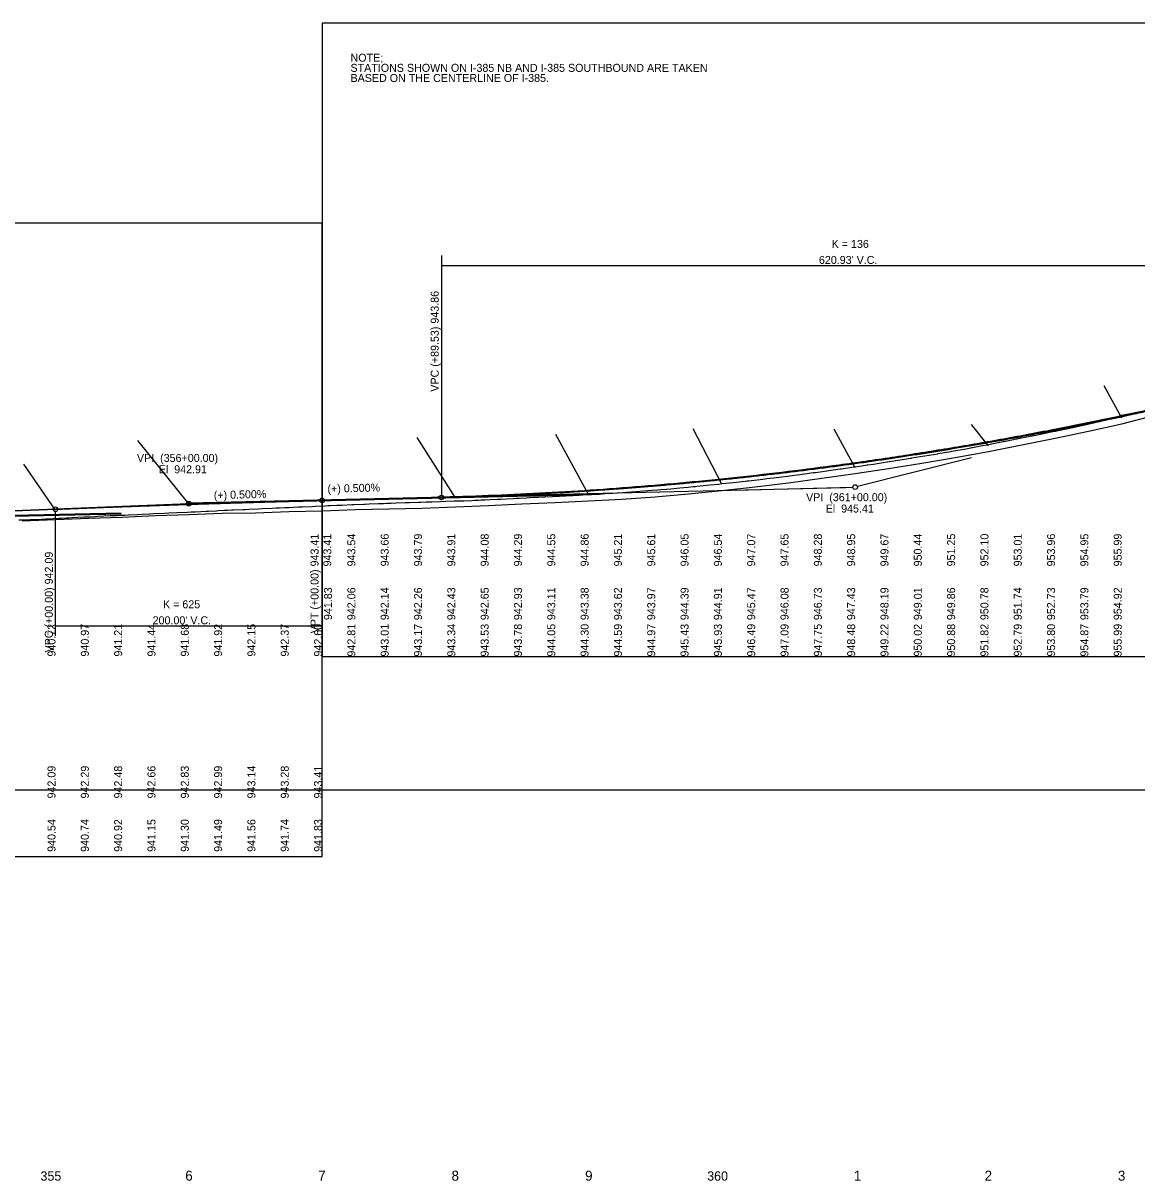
# Model space of a CAD drawing. Extents: x 120 to 1628239, y 505 to 1092823.
# Drawn here: x 1616014 to 1616850, y 1076164 to 1077032 of the extents above; entities that cross this region are included whole.
import ezdxf

# ---------------------------------------------------------------- set-up
doc = ezdxf.new("R2010")
doc.units = 0
for name, color, linetype in [('Default', 7, 'Continuous'), ('RD_DDB_GradeTX', 7, 'Continuous'), ('RD_DDB_PI', 7, 'Continuous'), ('RD_DDB_PR_Tx', 7, 'Continuous'), ('RD_DDB_Profile_EX', 7, 'Continuous'), ('RD_DDB_Profile_PR', 7, 'Continuous'), ('RD_DDB_StaTX', 7, 'Continuous'), ('RD_DDB_StripGrade', 7, 'Continuous'), ('RD_DDB_StripGrade_PR', 7, 'Continuous'), ('RD_DDB_VCLbl', 7, 'Continuous'), ('RD_GPK_Profile_Cell', 7, 'Continuous'), ('RD_PD_Final_TrvlWay', 7, 'Continuous'), ('RD_Sketch10', 7, 'Continuous')]:
    doc.layers.add(name, color=color, linetype=linetype)

msp = doc.modelspace()

# ---------------------------------------------------------------- linework, layer by layer
at = {"layer": 'Default'}
for p, q in [((1616138.64, 1076672.71), (1616631.44, 1076684.04)), ((1615838.64, 1076659.56), (1616138.64, 1076671.86)), ((1616238.64, 1076674.36), (1616318.64, 1076676.36)), ((1615938.64, 1076663.66), (1616038.64, 1076667.76))]:
    msp.add_line(p, q, dxfattribs=at)
for points in [[(1616238.64, 1076557.31), (1617738.64, 1076557.31), (1617738.64, 1077032.31), (1616238.64, 1077032.31)], [(1614738.64, 1076407.31), (1616238.64, 1076407.31), (1616238.64, 1076882.31), (1614738.64, 1076882.31)]]:
    msp.add_lwpolyline(points, close=True, dxfattribs=at)
for points in [[(1616318.64, 1076676.36), (1616638.64, 1076684.36), (1616958.64, 1076765.41)], [(1616320.44, 1076676.89), (1616631.44, 1076684.04), (1616942.44, 1076762.31)], [(1616038.64, 1076667.76), (1616138.64, 1076671.86), (1616238.64, 1076674.36)]]:
    msp.add_open_spline(points, degree=2, dxfattribs=at)
at = {"layer": 'RD_DDB_PI'}
for p, q in [((1616725.89, 1076706.46), (1616640.34, 1076684.79)), ((1616548.67, 1076682.11), (1616636.89, 1076684.31)), ((1616048.72, 1076668.17), (1616136.89, 1076671.79)), ((1616228.61, 1076674.11), (1616140.39, 1076671.9))]:
    msp.add_line(p, q, dxfattribs=at)
for centre in [(1616638.64, 1076684.36), (1616138.64, 1076671.86)]:
    msp.add_circle(centre, 1.75, dxfattribs=at)
at = {"layer": 'RD_DDB_Profile_EX'}
msp.add_lwpolyline([(1616013.64, 1076659.1), (1616038.64, 1076659.99), (1616063.64, 1076661.01), (1616088.64, 1076661.91), (1616113.64, 1076663.05), (1616138.64, 1076663.79), (1616163.64, 1076664.74), (1616188.64, 1076665.11), (1616213.64, 1076665.99), (1616238.64, 1076666.47), (1616263.64, 1076667.63), (1616288.64, 1076668.02), (1616313.64, 1076668.59), (1616338.64, 1076669.48), (1616363.64, 1076670.56), (1616388.64, 1076671.94), (1616413.64, 1076672.84), (1616438.64, 1076674.2), (1616463.64, 1076675.43), (1616488.64, 1076677.14), (1616513.64, 1076679.25), (1616538.64, 1076681.86), (1616563.64, 1076684.65), (1616588.64, 1076687.7), (1616613.64, 1076690.97), (1616638.64, 1076694.47), (1616663.64, 1076698.28), (1616688.64, 1076702.34), (1616713.64, 1076706.62), (1616738.64, 1076711.21), (1616763.64, 1076715.99), (1616788.64, 1076720.97), (1616813.64, 1076726.27), (1616838.64, 1076731.9), (1616863.64, 1076738.25)], dxfattribs=at)
at = {"layer": 'RD_DDB_Profile_PR'}
for p, q in [((1616238.64, 1076674.36), (1616328.18, 1076676.6)), ((1615938.64, 1076663.66), (1616038.64, 1076667.76))]:
    msp.add_line(p, q, dxfattribs=at)
for points in [[(1616328.18, 1076676.6), (1616340.59, 1076676.94), (1616353.01, 1076677.33), (1616365.43, 1076677.78), (1616377.85, 1076678.29), (1616390.27, 1076678.86), (1616402.69, 1076679.48), (1616415.11, 1076680.16), (1616427.52, 1076680.9), (1616439.94, 1076681.69), (1616452.36, 1076682.54), (1616464.78, 1076683.44), (1616477.2, 1076684.4), (1616489.62, 1076685.42), (1616502.04, 1076686.5), (1616514.46, 1076687.63), (1616526.87, 1076688.82), (1616539.29, 1076690.07), (1616551.71, 1076691.37), (1616564.13, 1076692.73), (1616576.55, 1076694.15), (1616588.97, 1076695.62), (1616601.39, 1076697.15), (1616613.8, 1076698.73), (1616626.22, 1076700.38), (1616638.64, 1076702.08), (1616651.06, 1076703.83), (1616663.48, 1076705.65), (1616675.9, 1076707.52), (1616688.32, 1076709.44), (1616700.73, 1076711.43), (1616713.15, 1076713.47), (1616725.57, 1076715.56), (1616737.99, 1076717.72), (1616750.41, 1076719.93), (1616762.83, 1076722.19), (1616775.25, 1076724.51), (1616787.67, 1076726.89), (1616800.08, 1076729.33), (1616812.5, 1076731.83), (1616824.92, 1076734.38), (1616837.34, 1076736.98), (1616849.76, 1076739.65), (1616862.18, 1076742.37), (1616874.6, 1076745.14), (1616887.01, 1076747.98), (1616899.43, 1076750.87), (1616911.85, 1076753.81), (1616924.27, 1076756.82), (1616936.69, 1076759.88), (1616949.11, 1076762.99)], [(1616038.64, 1076667.76), (1616042.64, 1076667.92), (1616046.64, 1076668.08), (1616050.64, 1076668.24), (1616054.64, 1076668.4), (1616058.64, 1076668.56), (1616062.64, 1076668.72), (1616066.64, 1076668.88), (1616070.64, 1076669.03), (1616074.64, 1076669.18), (1616078.64, 1076669.33), (1616082.64, 1076669.49), (1616086.64, 1076669.63), (1616090.64, 1076669.78), (1616094.64, 1076669.93), (1616098.64, 1076670.07), (1616102.64, 1076670.22), (1616106.64, 1076670.36), (1616110.64, 1076670.5), (1616114.64, 1076670.64), (1616118.64, 1076670.78), (1616122.64, 1076670.92), (1616126.64, 1076671.06), (1616130.64, 1076671.19), (1616134.64, 1076671.33), (1616138.64, 1076671.46), (1616142.64, 1076671.59), (1616146.64, 1076671.72), (1616150.64, 1076671.85), (1616154.64, 1076671.98), (1616158.64, 1076672.1), (1616162.64, 1076672.23), (1616166.64, 1076672.35), (1616170.64, 1076672.47), (1616174.64, 1076672.59), (1616178.64, 1076672.71), (1616182.64, 1076672.83), (1616186.64, 1076672.95), (1616190.64, 1076673.07), (1616194.64, 1076673.18), (1616198.64, 1076673.29), (1616202.64, 1076673.41), (1616206.64, 1076673.52), (1616210.64, 1076673.63), (1616214.64, 1076673.74), (1616218.64, 1076673.84), (1616222.64, 1076673.95), (1616226.64, 1076674.05), (1616230.64, 1076674.16), (1616234.64, 1076674.26), (1616238.64, 1076674.36)]]:
    msp.add_spline(points, degree=3, dxfattribs=at)
at = {"layer": 'RD_DDB_VCLbl'}
for p, q in [((1616328.18, 1076857.99), (1616328.18, 1076678.35)), ((1616328.18, 1076850.49), (1616949.11, 1076850.49)), ((1616238.64, 1076572.76), (1616238.64, 1076672.61)), ((1616038.64, 1076572.76), (1616038.64, 1076666.01)), ((1616038.64, 1076580.26), (1616238.64, 1076580.26))]:
    msp.add_line(p, q, dxfattribs=at)
for centre in [(1616328.18, 1076676.6), (1616038.64, 1076667.76), (1616238.64, 1076674.36)]:
    msp.add_circle(centre, 1.75, dxfattribs=at)
at = {"layer": 'RD_GPK_Profile_Cell'}
msp.add_line((1609538.64, 1076457.31), (1626874.64, 1076457.31), dxfattribs=at)
at = {"layer": 'RD_PD_Final_TrvlWay'}
for p, q in [((1616838.64, 1076736.06), (1616825.41, 1076760.22)), ((1616738.64, 1076715.46), (1616725.99, 1076731.3)), ((1616338.64, 1076676.36), (1616309.94, 1076721.59)), ((1616438.64, 1076678.76), (1616414.12, 1076723.93)), ((1616538.64, 1076686.51), (1616516.98, 1076728.03)), ((1616638.64, 1076698.86), (1616622.91, 1076727.8)), ((1616138.64, 1076671.86), (1616100.42, 1076719.25)), ((1616038.64, 1076667.06), (1616014.98, 1076701.68)), ((1616138.64, 1076672.71), (1616438.64, 1076679.61)), ((1616138.64, 1076671.86), (1616438.64, 1076678.76)), ((1616138.64, 1076671.86), (1615838.64, 1076659.56)), ((1614737.59, 1076634.58), (1616087.83, 1076665.19)), ((1614737.59, 1076633.73), (1616087.83, 1076664.34))]:
    msp.add_line(p, q, dxfattribs=at)
at = {"layer": 'RD_Sketch10'}
for points in [[(1616652.36, 1076701.71), (1616662.5, 1076703.26), (1616662.8, 1076703.3), (1616670.76, 1076704.55), (1616670.87, 1076704.57), (1616680.28, 1076706.12), (1616680.83, 1076706.21), (1616680.84, 1076706.22), (1616690.7, 1076707.76), (1616690.89, 1076707.79), (1616697.35, 1076708.88), (1616700.56, 1076709.44), (1616701.03, 1076709.52), (1616710.55, 1076711.15), (1616711.16, 1076711.27), (1616720.46, 1076712.9), (1616720.81, 1076712.96), (1616726.25, 1076714.03), (1616726.75, 1076714.12), (1616730.37, 1076714.77), (1616731.35, 1076714.97), (1616740.3, 1076716.71), (1616741, 1076716.83), (1616749.8, 1076718.59), (1616750.23, 1076718.67), (1616751.43, 1076718.91), (1616759.69, 1076720.46), (1616760.17, 1076720.56), (1616760.99, 1076720.72), (1616770.05, 1076722.55), (1616771.61, 1076722.87), (1616779.94, 1076724.49), (1616780.97, 1076724.71), (1616788.14, 1076726.23), (1616788.97, 1076726.4), (1616790.99, 1076726.79), (1616799.73, 1076728.63), (1616800.41, 1076728.78), (1616802.01, 1076729.1), (1616809.63, 1076730.71), (1616812.13, 1076731.3), (1616819.53, 1076733), (1616822.08, 1076733.6), (1616829.23, 1076735.23), (1616831.66, 1076735.71), (1616833.85, 1076736.16), (1616840.52, 1076737.69), (1616842.46, 1076738.17)], [(1616249.67, 1076670.73), (1616250.95, 1076670.79), (1616253.79, 1076670.94), (1616260.95, 1076671.25), (1616262.76, 1076671.35), (1616269.88, 1076671.59), (1616270.95, 1076671.65), (1616273.89, 1076671.78), (1616280.94, 1076672.1), (1616284.74, 1076672.19), (1616287.19, 1076672.31), (1616290.38, 1076672.46), (1616294.13, 1076672.58), (1616301.12, 1076672.82), (1616304.14, 1076672.91), (1616311.11, 1076673.07), (1616312.77, 1076673.13), (1616316.75, 1076673.27), (1616318.37, 1076673.32), (1616321.11, 1076673.36), (1616327.58, 1076673.55), (1616331.56, 1076673.72), (1616337.83, 1076673.99), (1616341.09, 1076674.06), (1616344.94, 1076674.19), (1616351.09, 1076674.46), (1616352.96, 1076674.55), (1616355.91, 1076674.66), (1616358.06, 1076674.75), (1616361.08, 1076674.86), (1616364.51, 1076675.01), (1616370.39, 1076675.29), (1616372.91, 1076675.4), (1616377.1, 1076675.59), (1616382.11, 1076675.87), (1616384.6, 1076675.98), (1616385.16, 1076676.01), (1616386.52, 1076676.1), (1616391.95, 1076676.42), (1616396.6, 1076676.72), (1616400.94, 1076676.93), (1616405.84, 1076677.18), (1616411.62, 1076677.44), (1616416.73, 1076677.69), (1616421.46, 1076677.92), (1616423.2, 1076678.03), (1616426.77, 1076678.17), (1616431.33, 1076678.42), (1616436.81, 1076678.75), (1616441, 1076678.93), (1616443.73, 1076679.05), (1616446.64, 1076679.2), (1616451.07, 1076679.47), (1616456.9, 1076679.82), (1616460.92, 1076680.05), (1616466.97, 1076680.49), (1616470.8, 1076680.77), (1616476.97, 1076681.24), (1616479.95, 1076681.49), (1616486.3, 1076681.99), (1616490.5, 1076682.32), (1616492.85, 1076682.52), (1616497.05, 1076682.9), (1616500.34, 1076683.2), (1616507.1, 1076683.82), (1616510.19, 1076684.16), (1616513.24, 1076684.43), (1616517.14, 1076684.82), (1616518.88, 1076684.95), (1616520.05, 1076685.06), (1616527.16, 1076685.79), (1616529.92, 1076686.08), (1616536.19, 1076686.7), (1616538.82, 1076686.98), (1616547.22, 1076687.87), (1616549.66, 1076688.13), (1616556.22, 1076688.83), (1616557.62, 1076688.99), (1616558.5, 1076689.09), (1616567.28, 1076690.19), (1616569.39, 1076690.45), (1616572.29, 1076690.73), (1616577.3, 1076691.34), (1616579.25, 1076691.57), (1616587.75, 1076692.65), (1616589.32, 1076692.85), (1616597.18, 1076693.88), (1616598.94, 1076694.11), (1616607.44, 1076695.22), (1616608.76, 1076695.39), (1616614.02, 1076696.14), (1616617.49, 1076696.59), (1616618.61, 1076696.75), (1616627.51, 1076697.99), (1616628.47, 1076698.14), (1616637.52, 1076699.53), (1616638.35, 1076699.64), (1616643.58, 1076700.38), (1616647.53, 1076701), (1616648.24, 1076701.12), (1616652.36, 1076701.71)], [(1616011.12, 1076659.75), (1616016.51, 1076659.91), (1616019.51, 1076660.05), (1616028.13, 1076660.39), (1616031.12, 1076660.55), (1616032.48, 1076660.63), (1616041.14, 1076661.06), (1616043.02, 1076661.18), (1616046.54, 1076661.35), (1616048.8, 1076661.46), (1616050.88, 1076661.59), (1616059.81, 1076661.97), (1616063.6, 1076662.17), (1616068.56, 1076662.43), (1616070.48, 1076662.54), (1616079.68, 1076662.98), (1616080.68, 1076663.04), (1616084.58, 1076663.14), (1616087.56, 1076663.31), (1616090.68, 1076663.44), (1616093.06, 1076663.56), (1616100.08, 1076663.86), (1616103.65, 1076664.07), (1616109.51, 1076664.33), (1616112.23, 1076664.47), (1616120.44, 1076664.79), (1616123.63, 1076665.01), (1616129.59, 1076665.3), (1616137.76, 1076665.66), (1616140.54, 1076665.79), (1616143.62, 1076665.95), (1616151.76, 1076666.32), (1616153.34, 1076666.42), (1616159.32, 1076666.7), (1616160.68, 1076666.8), (1616165.17, 1076666.98), (1616168.02, 1076667.14), (1616170.96, 1076667.23), (1616172.14, 1076667.3), (1616179.33, 1076667.61), (1616180.96, 1076667.71), (1616183.78, 1076667.84), (1616190.96, 1076668.16), (1616193.74, 1076668.33), (1616200.96, 1076668.64), (1616204.32, 1076668.83), (1616206.77, 1076668.95), (1616210.67, 1076669.02), (1616213.68, 1076669.18), (1616220.96, 1076669.52), (1616223.93, 1076669.68), (1616231.22, 1076669.95), (1616233.72, 1076670.09), (1616240.96, 1076670.41), (1616243.31, 1076670.59), (1616244.83, 1076670.65), (1616249.67, 1076670.73)]]:
    msp.add_lwpolyline(points, dxfattribs=at)

# ---------------------------------------------------------------- texts
at = {"layer": 'Default'}
for s, p in [('940.72', (1616038.64, 1076557.31)), ('940.97', (1616063.64, 1076557.31)), ('941.21', (1616088.64, 1076557.31)), ('941.44', (1616113.64, 1076557.31)), ('941.68', (1616138.64, 1076557.31)), ('941.92', (1616163.64, 1076557.31)), ('942.15', (1616188.64, 1076557.31)), ('942.37', (1616213.64, 1076557.31)), ('942.60', (1616238.64, 1076557.31)), ('942.81', (1616263.64, 1076557.31)), ('943.01', (1616288.64, 1076557.31)), ('943.17', (1616313.64, 1076557.31)), ('943.34', (1616338.64, 1076557.31)), ('943.53', (1616363.64, 1076557.31)), ('943.78', (1616388.64, 1076557.31)), ('944.05', (1616413.64, 1076557.31)), ('944.30', (1616438.64, 1076557.31)), ('944.59', (1616463.64, 1076557.31)), ('944.97', (1616488.64, 1076557.31)), ('945.43', (1616513.64, 1076557.31)), ('945.93', (1616538.64, 1076557.31)), ('946.49', (1616563.64, 1076557.31)), ('947.09', (1616588.64, 1076557.31)), ('947.75', (1616613.64, 1076557.31)), ('948.48', (1616638.64, 1076557.31)), ('949.22', (1616663.64, 1076557.31)), ('950.02', (1616688.64, 1076557.31)), ('950.88', (1616713.64, 1076557.31)), ('951.82', (1616738.64, 1076557.31)), ('952.79', (1616763.64, 1076557.31)), ('953.80', (1616788.64, 1076557.31)), ('954.87', (1616813.64, 1076557.31)), ('955.99', (1616838.64, 1076557.31))]:
    msp.add_text(s, height=6, rotation=90, dxfattribs=at).set_placement(p)
at = {"layer": 'RD_DDB_GradeTX'}
for p in [(1616242.78, 1076680.14), (1616157.47, 1076675.33)]:
    msp.add_text('(+) 0.500%', height=6, rotation=1.4321, dxfattribs=at).set_placement(p)
at = {"layer": 'RD_DDB_PI'}
for s, p in [('VPI  (356+00.00)', (1616099.75, 1076703.26)), ('El  942.91', (1616116.11, 1076694.76)), ('VPI  (361+00.00)', (1616601.82, 1076673.81)), ('El  945.41', (1616616.53, 1076665.31))]:
    msp.add_text(s, height=6, dxfattribs=at).set_placement(p)
at = {"layer": 'RD_DDB_PR_Tx'}
for s, p in [('NOTE;', (1616259.99, 1077003.4)), ('STATIONS SHOWN ON I-385 NB AND I-385 SOUTHBOUND ARE TAKEN', (1616259.99, 1076995.79)), ('BASED ON THE CENTERLINE OF I-385.', (1616259.99, 1076988.19))]:
    msp.add_text(s, height=6, dxfattribs=at).set_placement(p)
at = {"layer": 'RD_DDB_StaTX'}
for s, height, p in [('355', 7, (1616027.36, 1076164.25)), ('6', 7.5, (1616136, 1076164.25)), ('7', 7.5, (1616235.76, 1076164.25)), ('8', 7.5, (1616335.8, 1076164.25)), ('9', 7.5, (1616436, 1076164.25)), ('360', 7, (1616527.6, 1076164.25)), ('1', 7.5, (1616637.64, 1076164.25)), ('2', 7.5, (1616735.8, 1076164.25)), ('3', 7.5, (1616835.8, 1076164.25))]:
    msp.add_text(s, height=height, dxfattribs=at).set_placement(p)
at = {"layer": 'RD_DDB_StripGrade'}
for s, p in [('941.83', (1616246.07, 1076584.67)), ('942.06', (1616263.64, 1076584.62)), ('942.14', (1616288.64, 1076584.62)), ('942.26', (1616313.64, 1076584.62)), ('942.43', (1616338.64, 1076584.62)), ('942.65', (1616363.64, 1076584.62)), ('942.93', (1616388.64, 1076584.62)), ('943.11', (1616413.64, 1076584.62)), ('943.38', (1616438.64, 1076584.62)), ('943.62', (1616463.64, 1076584.62)), ('943.97', (1616488.64, 1076584.62)), ('944.39', (1616513.64, 1076584.62)), ('944.91', (1616538.64, 1076584.62)), ('945.47', (1616563.64, 1076584.62)), ('946.08', (1616588.64, 1076584.62)), ('946.73', (1616613.64, 1076584.62)), ('947.43', (1616638.64, 1076584.62)), ('948.19', (1616663.64, 1076584.62)), ('949.01', (1616688.64, 1076584.62)), ('949.86', (1616713.64, 1076584.62)), ('950.78', (1616738.64, 1076584.62)), ('951.74', (1616763.64, 1076584.62)), ('952.73', (1616788.64, 1076584.62)), ('953.79', (1616813.64, 1076584.62)), ('954.92', (1616838.64, 1076584.62)), ('940.54', (1616038.64, 1076410.85)), ('940.74', (1616063.64, 1076410.85)), ('940.92', (1616088.64, 1076410.85)), ('941.15', (1616113.64, 1076410.85)), ('941.30', (1616138.64, 1076410.85)), ('941.49', (1616163.64, 1076410.85)), ('941.56', (1616188.64, 1076410.85)), ('941.74', (1616213.64, 1076410.85)), ('941.83', (1616238.64, 1076410.85))]:
    msp.add_text(s, height=6, rotation=90, dxfattribs=at).set_placement(p)
at = {"layer": 'RD_DDB_StripGrade_PR'}
for s, p in [('943.41', (1616245.59, 1076624.86)), ('943.54', (1616263.64, 1076624.93)), ('943.66', (1616288.64, 1076624.93)), ('943.79', (1616313.64, 1076624.93)), ('943.91', (1616338.64, 1076624.93)), ('944.08', (1616363.64, 1076624.93)), ('944.29', (1616388.64, 1076624.93)), ('944.55', (1616413.64, 1076624.93)), ('944.86', (1616438.64, 1076624.93)), ('945.21', (1616463.64, 1076624.93)), ('945.61', (1616488.64, 1076624.93)), ('946.05', (1616513.64, 1076624.93)), ('946.54', (1616538.64, 1076624.93)), ('947.07', (1616563.64, 1076624.93)), ('947.65', (1616588.64, 1076624.93)), ('948.28', (1616613.64, 1076624.93)), ('948.95', (1616638.64, 1076624.93)), ('949.67', (1616663.64, 1076624.93)), ('950.44', (1616688.64, 1076624.93)), ('951.25', (1616713.64, 1076624.93)), ('952.10', (1616738.64, 1076624.93)), ('953.01', (1616763.64, 1076624.93)), ('953.96', (1616788.64, 1076624.93)), ('954.95', (1616813.64, 1076624.93)), ('955.99', (1616838.64, 1076624.93)), ('942.09', (1616038.64, 1076450.9)), ('942.29', (1616063.64, 1076450.9)), ('942.48', (1616088.64, 1076450.9)), ('942.66', (1616113.64, 1076450.9)), ('942.83', (1616138.64, 1076450.9)), ('942.99', (1616163.64, 1076450.9)), ('943.14', (1616188.64, 1076450.9)), ('943.28', (1616213.64, 1076450.9)), ('943.41', (1616238.64, 1076450.9))]:
    msp.add_text(s, height=6, rotation=90, dxfattribs=at).set_placement(p)
at = {"layer": 'RD_DDB_VCLbl'}
for s, p in [('K = 136', (1616621.02, 1076863.74)), ("620.93' V.C.", (1616611.45, 1076851.74)), ('K = 625', (1616119.31, 1076593.51)), ("200.00' V.C.", (1616111.51, 1076581.51))]:
    msp.add_text(s, height=6, dxfattribs=at).set_placement(p)
for s, p in [('VPC (+89.53) 943.86', (1616326.18, 1076755.92)), ('VPT (+00.00) 943.41', (1616236.02, 1076574.71)), ('VPC (+00.00) 942.09', (1616036.64, 1076560.36))]:
    msp.add_text(s, height=6, rotation=90, dxfattribs=at).set_placement(p)

doc.saveas('drawing.dxf')
